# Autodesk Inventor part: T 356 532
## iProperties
_DisabledCommands: 0
Created: 2005-12
Part Number: T 356 532
Material: 1.4301
Description: Bolzen
Vendor: Autodesk Inc.
Document SubType Name: Modeling
Standard: DIN 671
Designer: I.Baliuc
Size Designation: 10 - 84
Density: 7.86 g/cm^3
HalbzeugNorm: DIN 671
Abmessung: Rd 10 - 84
Author: T.Messerschmitt
Keywords: 266187
Revision Number: 356532
Comments: DIN 671 / 10 - 84
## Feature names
1. Körper [Extrusion]
2. Bohrung_M8x12_1 [Hole]
3. Bohrung_M8x12_2 [Hole]
